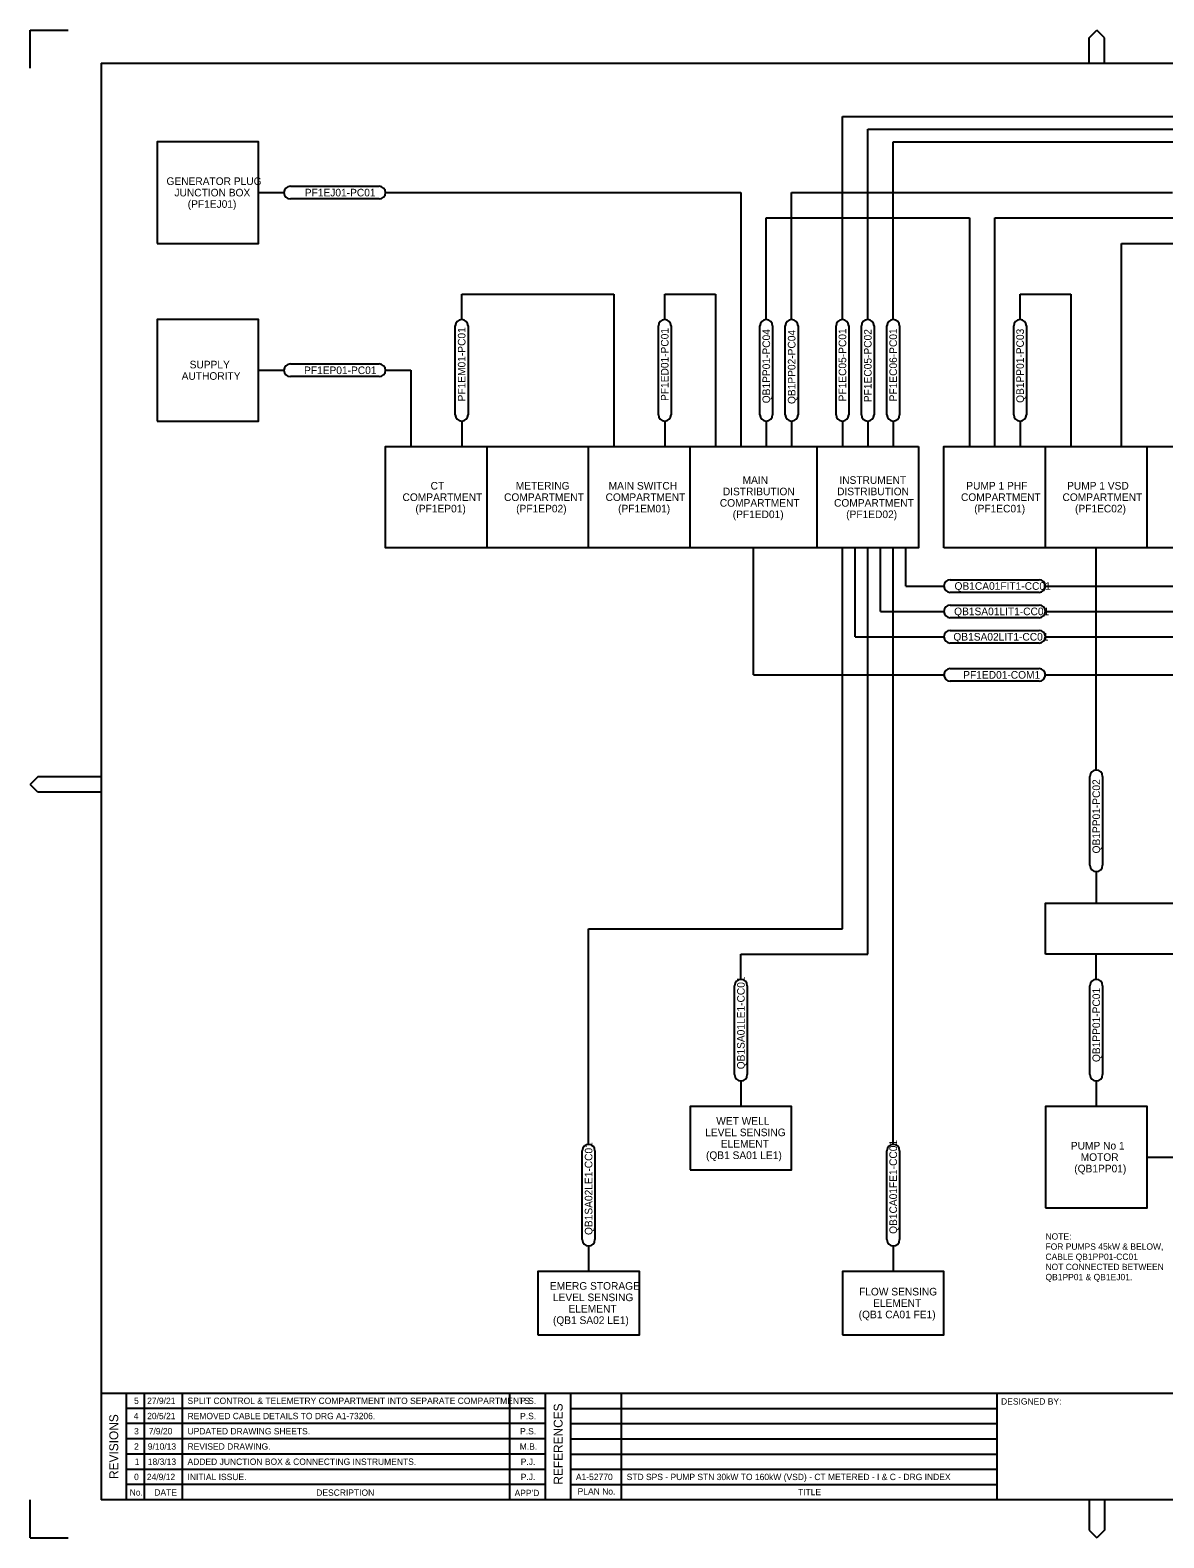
# Model space of a CAD drawing. Extents: x 0 to 841, y 0 to 594.
# Drawn here: x 0 to 447, y 0 to 594 of the extents above; entities that cross this region are included whole.
import ezdxf

# ---------------------------------------------------------------- set-up
doc = ezdxf.new("R2010")
doc.units = 0
for name, color, linetype in [('A1BORDER', 7, 'Continuous'), ('INSTALLED', 7, 'Continuous'), ('Level 1', 7, 'Continuous')]:
    doc.layers.add(name, color=color, linetype=linetype)

msp = doc.modelspace()

# ---------------------------------------------------------------- linework, layer by layer
at = {"layer": 'A1BORDER'}
for p, q in [((0, 594), (15, 594)), ((0, 579), (0, 594)), ((417.19, 591), (420.19, 594)), ((423.19, 591), (420.19, 594)), ((417.19, 581), (417.19, 591)), ((423.19, 581), (423.19, 591)), ((28, 581), (829, 581)), ((28, 581), (28, 15)), ((3, 299.76), (0, 296.76)), ((28, 299.76), (3, 299.76)), ((3, 293.76), (0, 296.76)), ((28, 293.76), (3, 293.76)), ((28, 57), (829, 57)), ((38, 15), (38, 57)), ((45, 15), (45, 57)), ((60, 15), (60, 57)), ((189, 15), (189, 57)), ((203, 15), (203, 57)), ((213, 15), (213, 57)), ((233, 15), (233, 57)), ((381, 15), (381, 57)), ((203, 51), (38, 51)), ((213, 51), (381, 51)), ((203, 45), (38, 45)), ((213, 45), (381, 45)), ((203, 39), (38, 39)), ((213, 39), (381, 39)), ((203, 33), (38, 33)), ((213, 33), (381, 33)), ((38, 27), (203, 27)), ((213, 27), (381, 27)), ((203, 21), (38, 21)), ((213, 21), (381, 21)), ((0, 0), (0, 15)), ((829, 15), (28, 15)), ((417.19, 15), (417.19, 3)), ((423.19, 15), (423.19, 3)), ((0, 0), (15, 0)), ((417.19, 3), (420.19, 0)), ((423.19, 3), (420.19, 0))]:
    msp.add_line(p, q, dxfattribs=at)
at = {"layer": 'INSTALLED'}
for p, q in [((320, 480), (320, 560)), ((320, 560), (740, 560)), ((330, 480), (330, 555)), ((330, 555), (645, 555)), ((340, 480), (340, 550)), ((340, 550), (635, 550)), ((90, 530), (100, 530)), ((102.5, 532.5), (137.5, 532.5)), ((140, 530), (280, 530)), ((280, 530), (280, 430)), ((300, 480), (300, 530)), ((300, 530), (450, 530)), ((137.5, 527.5), (102.5, 527.5)), ((290, 480), (290, 520)), ((290, 520), (370, 520)), ((370, 520), (370, 430)), ((380, 430), (380, 520)), ((380, 520), (515, 520)), ((430, 430), (430, 510)), ((430, 510), (515, 510)), ((170, 480), (170, 490)), ((170, 490), (230, 490)), ((170, 490), (230, 490)), ((230, 490), (230, 430)), ((250, 480), (250, 490)), ((250, 490), (270, 490)), ((270, 490), (270, 430)), ((390, 480), (390, 490)), ((390, 490), (410, 490)), ((410, 490), (410, 430)), ((167.5, 442.5), (167.5, 477.5)), ((172.5, 477.5), (172.5, 442.5)), ((247.5, 442.5), (247.5, 477.5)), ((252.5, 477.5), (252.5, 442.5)), ((287.5, 442.5), (287.5, 477.5)), ((292.5, 477.5), (292.5, 442.5)), ((297.5, 442.5), (297.5, 477.5)), ((302.5, 477.5), (302.5, 442.5)), ((317.5, 442.5), (317.5, 477.5)), ((322.5, 477.5), (322.5, 442.5)), ((327.5, 442.5), (327.5, 477.5)), ((332.5, 477.5), (332.5, 442.5)), ((337.5, 442.5), (337.5, 477.5)), ((342.5, 477.5), (342.5, 442.5)), ((387.5, 442.5), (387.5, 477.5)), ((392.5, 477.5), (392.5, 442.5)), ((90, 460), (100, 460)), ((102.5, 462.5), (137.5, 462.5)), ((137.5, 457.5), (102.5, 457.5)), ((140, 460), (150, 460)), ((150, 460), (150, 430)), ((170, 440), (170, 430)), ((250, 440), (250, 430)), ((290, 440), (290, 430)), ((300, 440), (300, 430)), ((320, 440), (320, 430)), ((330, 440), (330, 430)), ((340, 440), (340, 430)), ((390, 440), (390, 430)), ((180, 390), (180, 430)), ((220, 390), (220, 430)), ((260, 390), (260, 430)), ((310, 390), (310, 430)), ((400, 390), (400, 430)), ((440, 390), (440, 430)), ((285, 340), (285, 390)), ((320, 240), (320, 390)), ((325, 355), (325, 390)), ((330, 230), (330, 390)), ((335, 365), (335, 390)), ((340, 155), (340, 390)), ((345, 375), (345, 390)), ((420, 302.5), (420, 390)), ((345, 375), (360, 375)), ((362.5, 377.5), (397.5, 377.5)), ((400, 375), (560, 375)), ((397.5, 372.5), (362.5, 372.5)), ((335, 365), (360, 365)), ((362.5, 367.5), (397.5, 367.5)), ((397.5, 362.5), (362.5, 362.5)), ((400, 365), (570, 365)), ((362.5, 357.5), (397.5, 357.5)), ((325, 355), (360, 355)), ((397.5, 352.5), (362.5, 352.5)), ((400, 355), (580, 355)), ((285, 340), (360, 340)), ((362.5, 342.5), (397.5, 342.5)), ((400, 340), (600, 340)), ((397.5, 337.5), (362.5, 337.5)), ((417.5, 265), (417.5, 300)), ((422.5, 300), (422.5, 265)), ((420, 262.5), (420, 250)), ((220, 155), (220, 240)), ((220, 240), (320, 240)), ((280, 220), (280, 230)), ((280, 230), (330, 230)), ((420, 220), (420, 230)), ((277.5, 182.5), (277.5, 217.5)), ((282.5, 217.5), (282.5, 182.5)), ((417.5, 182.5), (417.5, 217.5)), ((422.5, 217.5), (422.5, 182.5)), ((280, 180), (280, 170)), ((420, 180), (420, 170)), ((217.5, 117.5), (217.5, 152.5)), ((222.5, 152.5), (222.5, 117.5)), ((337.5, 117.5), (337.5, 152.5)), ((342.5, 152.5), (342.5, 117.5)), ((440, 150), (460, 150)), ((220, 115), (220, 105)), ((340, 115), (340, 105))]:
    msp.add_line(p, q, dxfattribs=at)
for points in [[(50, 510), (90, 510), (90, 550), (50, 550)], [(50, 440), (90, 440), (90, 480), (50, 480)], [(350, 430), (350, 390), (140, 390), (140, 430)], [(360, 390), (360, 430), (800, 430), (800, 390)], [(400, 230), (400, 250), (810, 250), (810, 230)], [(260, 145), (300, 145), (300, 170), (260, 170)], [(400, 130), (440, 130), (440, 170), (400, 170)], [(200, 80), (240, 80), (240, 105), (200, 105)], [(320, 80), (360, 80), (360, 105), (320, 105)]]:
    msp.add_lwpolyline(points, close=True, dxfattribs=at)
for centre, start, end in [((102.5, 530), 90, 270), ((137.5, 530), 270, 90), ((170, 477.5), 0, 180), ((250, 477.5), 0, 180), ((290, 477.5), 0, 180), ((300, 477.5), 0, 180), ((320, 477.5), 0, 180), ((330, 477.5), 0, 180), ((340, 477.5), 0, 180), ((390, 477.5), 0, 180), ((102.5, 460), 90, 270), ((137.5, 460), 270, 90), ((170, 442.5), 180, 0), ((250, 442.5), 180, 0), ((290, 442.5), 180, 0), ((300, 442.5), 180, 0), ((320, 442.5), 180, 0), ((330, 442.5), 180, 0), ((340, 442.5), 180, 0), ((390, 442.5), 180, 0), ((362.5, 375), 90, 270), ((397.5, 375), 270, 90), ((362.5, 365), 90, 270), ((397.5, 365), 270, 90), ((362.5, 355), 90, 270), ((397.5, 355), 270, 90), ((362.5, 340), 90, 270), ((397.5, 340), 270, 90), ((420, 300), 0, 180), ((420, 265), 180, 0), ((280, 217.5), 0, 180), ((420, 217.5), 0, 180), ((280, 182.5), 180, 0), ((420, 182.5), 180, 0), ((220, 152.5), 0, 180), ((340, 152.5), 0, 180), ((220, 117.5), 180, 0), ((340, 117.5), 180, 0)]:
    msp.add_arc(centre, 2.5, start, end, dxfattribs=at)

# ---------------------------------------------------------------- texts
at = {"layer": 'A1BORDER'}
for s, p in [('DESIGNED BY:', (382.5, 52.5)), ('No.', (39.21, 16.65)), ('DATE', (48.92, 16.65)), ('DESCRIPTION', (112.71, 16.57)), ("APP'D", (190.85, 16.44)), ('PLAN No.', (215.69, 17.06)), ('TITLE', (302.5, 16.81))]:
    msp.add_text(s, height=2.5, dxfattribs=at).set_placement(p)
for s, p in [('REVISIONS', (34.68, 23.2)), ('REFERENCES', (209.76, 20.96))]:
    msp.add_text(s, height=3.5, rotation=90, dxfattribs=at).set_placement(p)
at = {"layer": 'INSTALLED'}
for s, height, p in [('GENERATOR PLUG', 3, (53.71, 533)), ('JUNCTION BOX', 3, (56.85, 528.5)), ('PF1EJ01-PC01', 3, (108.2, 528.5)), ('(PF1EJ01)', 3, (62.08, 524)), ('SUPPLY', 3, (62.83, 460.75)), ('AUTHORITY', 3, (59.69, 456.25)), ('PF1EP01-PC01', 3, (107.9, 458.5)), ('MAIN', 3, (280.67, 415.25)), ('INSTRUMENT', 3, (318.79, 415.25)), ('DISTRIBUTION', 3, (272.9, 410.75)), ('DISTRIBUTION', 3, (317.9, 410.75)), ('COMPARTMENT', 3, (271.7, 406.25)), ('(PF1ED01)', 3, (276.78, 401.75)), ('COMPARTMENT', 3, (316.7, 406.25)), ('(PF1ED02)', 3, (321.48, 401.75)), ('QB1CA01FIT1-CC01', 3, (364.16, 373.5)), ('QB1SA01LIT1-CC01', 3, (364.01, 363.5)), ('QB1SA02LIT1-CC01', 3, (363.71, 353.5)), ('PF1ED01-COM1', 3, (367.6, 338.5)), ('LEVEL SENSING', 3, (265.96, 158.25)), ('WET WELL', 3, (270.29, 162.75)), ('ELEMENT', 3, (272.08, 153.75)), ('PUMP No 1', 3, (409.99, 153)), ('(QB1 SA01 LE1)', 3, (266.25, 149.25)), ('MOTOR', 3, (413.87, 148.5)), ('(QB1PP01)', 3, (411.33, 144)), ('NOTE:', 2.5, (400, 117.5)), ('FOR PUMPS 45kW & BELOW,', 2.5, (400, 113.5)), ('CABLE QB1PP01-CC01', 2.5, (400, 109.5)), ('NOT CONNECTED BETWEEN', 2.5, (400, 105.5)), ('QB1PP01 & QB1EJ01.', 2.5, (400, 101.5)), ('EMERG STORAGE', 3, (204.76, 97.75)), ('LEVEL SENSING', 3, (205.96, 93.25)), ('FLOW SENSING', 3, (326.55, 95.5)), ('ELEMENT', 3, (212.08, 88.75)), ('(QB1 CA01 FE1)', 3, (326.4, 86.5)), ('ELEMENT', 3, (332.08, 91)), ('(QB1 SA02 LE1)', 3, (205.96, 84.25))]:
    msp.add_text(s, height=height, dxfattribs=at).set_placement(p)
for s, rotation, p in [('PF1EM01-PC01', 90, (171.5, 447.75)), ('PF1ED01-PC01', 90, (251.5, 447.9)), ('QB1PP01-PC04', 90, (291.5, 447)), ('QB1PP02-PC04', 90, (301.5, 446.7)), ('PF1EC05-PC01', 90, (321.5, 447.75)), ('PF1EC05-PC02', 90, (331.5, 447.45)), ('PF1EC06-PC01', 90, (341.5, 447.75)), ('QB1PP01-PC03', 90, (391.5, 447.15)), ('CT', 360, (157.76, 413)), ('METERING', 360, (191.33, 413)), ('MAIN SWITCH', 360, (227.9, 413)), ('PUMP 1 PHF', 360, (368.79, 413)), ('PUMP 1 VSD', 360, (408.5, 413)), ('COMPARTMENT', 360, (146.7, 408.5)), ('COMPARTMENT', 360, (186.7, 408.5)), ('COMPARTMENT', 360, (226.7, 408.5)), ('COMPARTMENT', 360, (366.7, 408.5)), ('COMPARTMENT', 360, (406.7, 408.5)), ('(PF1EP01)', 360, (151.78, 404)), ('(PF1EP02)', 360, (191.48, 404)), ('(PF1EM01)', 360, (231.63, 404)), ('(PF1EC01)', 360, (371.93, 404)), ('(PF1EC02)', 360, (411.63, 404)), ('QB1PP01-PC02', 90, (421.5, 269.65)), ('QB1SA01LE1-CC01', 90, (281.5, 184.61)), ('QB1PP01-PC01', 90, (421.5, 187.45)), ('QB1SA02LE1-CC01', 90, (221.5, 119.31)), ('QB1CA01FE1-CC01', 90, (341.5, 119.76))]:
    msp.add_text(s, height=3, rotation=rotation, dxfattribs=at).set_placement(p)
at = {"layer": 'Level 1'}
for s, p in [('5', (40.94, 52.75)), ('27/9/21', (46.09, 52.75)), ('SPLIT CONTROL & TELEMETRY COMPARTMENT INTO SEPARATE COMPARTMENTS.', (62, 52.75)), ('P.S.', (193.02, 52.75)), ('4', (40.82, 46.75)), ('20/5/21', (46.09, 46.75)), ('REMOVED CABLE DETAILS TO DRG A1-73206.', (62, 46.75)), ('P.S.', (193.02, 46.75)), ('3', (40.94, 40.75)), ('7/9/20', (46.72, 40.75)), ('UPDATED DRAWING SHEETS.', (62, 40.75)), ('P.S.', (193.02, 40.75)), ('2', (40.94, 34.75)), ('9/10/13', (46.34, 34.75)), ('REVISED DRAWING.', (62, 34.75)), ('M.B.', (192.89, 34.75)), ('1', (41.19, 28.75)), ('18/3/13', (46.34, 28.75)), ('ADDED JUNCTION BOX & CONNECTING INSTRUMENTS.', (62, 28.75)), ('P.J.', (193.26, 28.75)), ('0', (40.94, 22.75)), ('24/9/12', (45.97, 22.75)), ('INITIAL ISSUE.', (62, 22.75)), ('P.J.', (193.26, 22.75)), ('A1-52770', (215, 22.75)), ('STD SPS - PUMP STN 30kW TO 160kW (VSD) - CT METERED - I & C - DRG INDEX', (235, 22.75))]:
    msp.add_text(s, height=2.5, dxfattribs=at).set_placement(p)

doc.saveas('drawing.dxf')
